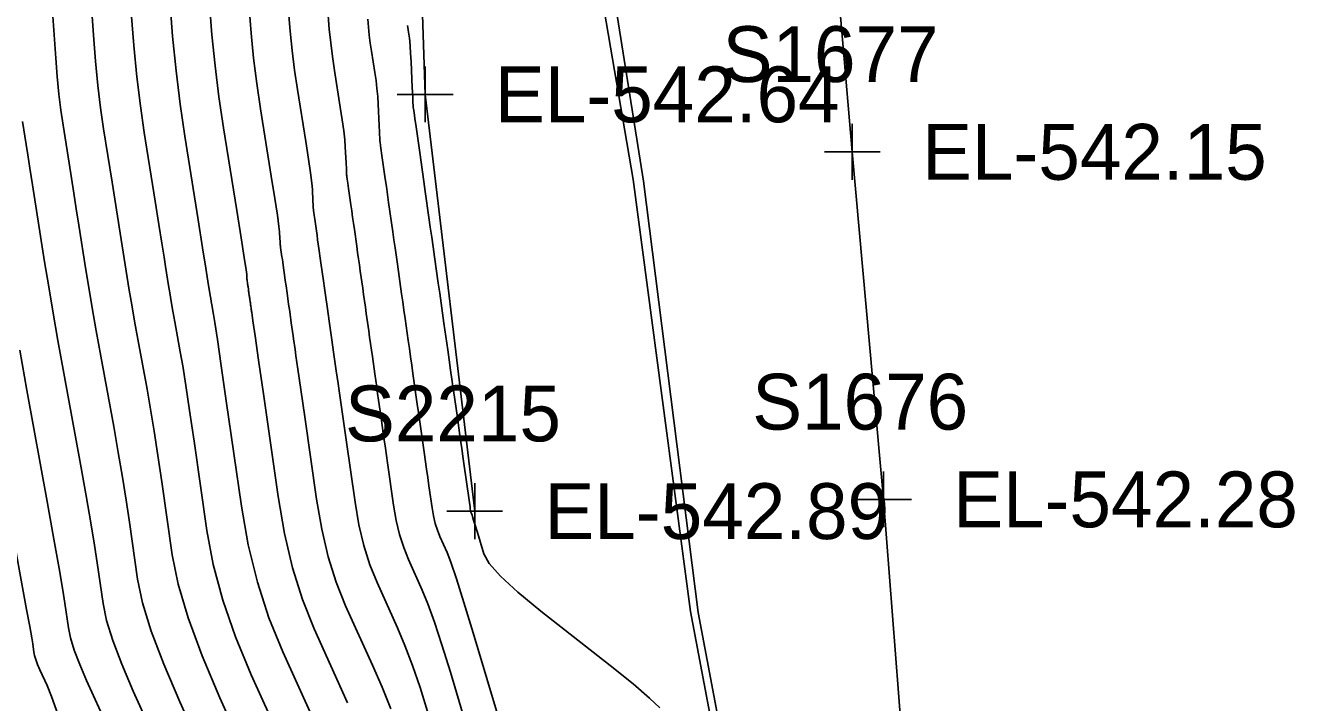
# Model space of a CAD drawing. Extents: x 1724534 to 1727318, y 657156 to 660047.
# Drawn here: x 1725501.3 to 1725592.2, y 658724.9 to 658773.4 of the extents above; entities that cross this region are included whole.
import ezdxf

# ---------------------------------------------------------------- set-up
doc = ezdxf.new("R2010")
doc.units = 0
for name, color, linetype in [('SURVEY - CONTOURS - Index with Text', 7, 'Continuous'), ('SURVEY - CONTOURS - Intermediate with optional Text', 7, 'Continuous'), ('SURVEY - DTM - Breaklines', 7, 'Continuous'), ('SURVEY - DTM - Breaklines - Points - Elevations', 7, 'Continuous'), ('SURVEY - DTM - Breaklines - Points - Locators', 7, 'Continuous'), ('SURVEY - DTM - Breaklines - Points - Numbers', 7, 'Continuous'), ('SURVEY - TRANSPORTATION - Features', 7, 'Continuous'), ('SURVEY - TRANSPORTATION - Features - Points - Elevations', 7, 'Continuous'), ('SURVEY - TRANSPORTATION - Features - Points - Locators', 7, 'Continuous'), ('SURVEY - TRANSPORTATION - Features - Points - Numbers', 7, 'Continuous'), ('SURVEY - UTILITIES - Electric (Underground) with Text', 7, 'Continuous'), ('SURVEY - UTILITIES - Fiber Optic Cable (Underground) with Text', 7, 'Continuous')]:
    doc.layers.add(name, color=color, linetype=linetype)

msp = doc.modelspace()

# ---------------------------------------------------------------- linework, layer by layer
at = {"layer": 'SURVEY - CONTOURS - Index with Text'}
for points in [[(1725508.859, 658774.321), (1725509.045, 658771.934), (1725509.261, 658769.703), (1725509.507, 658767.628), (1725509.785, 658765.709), (1725510.567, 658760.8), (1725510.833, 658759.126), (1725511.046, 658757.786), (1725511.206, 658756.779), (1725511.313, 658756.107), (1725511.526, 658754.758), (1725511.614, 658754.214), (1725511.719, 658753.597), (1725511.84, 658752.905), (1725511.978, 658752.138), (1725512.368, 658749.995), (1725512.539, 658748.992), (1725512.76, 658747.59), (1725513.03, 658745.79), (1725513.35, 658743.591), (1725514.268, 658737.195), (1725514.725, 658734.75), (1725515.409, 658732.214), (1725516.319, 658729.585), (1725517.455, 658726.864), (1725519.5, 658722.336)], [(1725522.963, 658774.097), (1725523.042, 658773.114), (1725523.143, 658772.13), (1725523.267, 658771.146), (1725523.412, 658770.162), (1725523.83, 658767.536), (1725523.97, 658766.619), (1725524.076, 658765.839), (1725524.148, 658765.194), (1725524.186, 658764.685), (1725524.243, 658763.51), (1725524.261, 658763.123), (1725524.275, 658762.846), (1725524.283, 658762.676), (1725524.287, 658762.616), (1725524.289, 658762.599), (1725524.298, 658762.539), (1725524.322, 658762.37), (1725524.361, 658762.093), (1725524.416, 658761.707), (1725524.582, 658760.533), (1725524.645, 658760.092), (1725524.708, 658759.65), (1725524.771, 658759.205), (1725524.834, 658758.76), (1725525.003, 658757.569), (1725525.067, 658757.121), (1725525.131, 658756.672), (1725525.195, 658756.222), (1725525.259, 658755.769), (1725525.431, 658754.561), (1725525.495, 658754.107), (1725525.56, 658753.651), (1725525.625, 658753.194), (1725525.69, 658752.735), (1725525.864, 658751.509), (1725525.93, 658751.048), (1725525.995, 658750.586), (1725526.061, 658750.122), (1725526.127, 658749.656), (1725526.304, 658748.411), (1725526.37, 658747.944), (1725526.437, 658747.474), (1725526.504, 658747.003), (1725526.571, 658746.53), (1725526.751, 658745.267), (1725526.83, 658744.71), (1725526.933, 658743.989), (1725527.06, 658743.101), (1725527.211, 658742.049), (1725527.646, 658739.021), (1725527.835, 658737.925), (1725528.076, 658736.908), (1725528.368, 658735.97), (1725528.712, 658735.111), (1725529.7, 658732.924), (1725530.103, 658731.941), (1725530.573, 658730.634), (1725531.108, 658729.003), (1725531.71, 658727.046), (1725533.403, 658721.396)], [(1725500.188, 658737.991), (1725501.361, 658731.538), (1725501.58, 658730.321), (1725501.723, 658729.502), (1725501.793, 658729.081), (1725501.878, 658728.489), (1725501.929, 658728.243), (1725502.02, 658727.948), (1725502.149, 658727.604), (1725502.318, 658727.211), (1725502.82, 658726.099), (1725503.139, 658725.293), (1725503.72, 658723.709), (1725504.564, 658721.345), (1725505.669, 658718.204), (1725506.416, 658716.07)]]:
    msp.add_lwpolyline(points, dxfattribs=at)
at = {"layer": 'SURVEY - CONTOURS - Intermediate with optional Text'}
for points in [[(1725505.802, 658777.801), (1725506.154, 658772.682), (1725506.299, 658770.823), (1725506.467, 658769.086), (1725506.659, 658767.47), (1725506.875, 658765.976), (1725507.484, 658762.153), (1725508.063, 658758.508), (1725508.209, 658757.585), (1725508.567, 658755.319), (1725508.715, 658754.406), (1725508.892, 658753.368), (1725509.096, 658752.205), (1725509.327, 658750.917), (1725509.983, 658747.316), (1725510.233, 658745.889), (1725510.492, 658744.309), (1725510.761, 658742.575), (1725511.038, 658740.689), (1725511.79, 658735.454), (1725512.215, 658733.341), (1725512.925, 658730.931), (1725513.922, 658728.222), (1725515.204, 658725.215), (1725519.004, 658716.798)], [(1725503.197, 658774.708), (1725503.45, 658771.043), (1725503.553, 658769.713), (1725503.673, 658768.469), (1725503.811, 658767.312), (1725503.966, 658766.242), (1725504.402, 658763.505), (1725504.741, 658761.369), (1725504.92, 658760.237), (1725505.106, 658759.064), (1725505.609, 658755.88), (1725505.817, 658754.598), (1725506.064, 658753.14), (1725506.351, 658751.506), (1725506.677, 658749.697), (1725507.597, 658744.637), (1725507.927, 658742.786), (1725508.225, 658741.027), (1725508.492, 658739.361), (1725508.727, 658737.787), (1725509.312, 658733.713), (1725509.666, 658732.017), (1725510.289, 658729.986), (1725511.181, 658727.619), (1725512.342, 658724.917), (1725515.798, 658717.265)], [(1725511.617, 658775.195), (1725511.82, 658772.614), (1725512.067, 658770.129), (1725512.359, 658767.738), (1725512.695, 658765.443), (1725513.649, 658759.448), (1725513.966, 658757.46), (1725514.199, 658755.995), (1725514.349, 658755.05), (1725514.512, 658754.023), (1725514.546, 658753.825), (1725514.585, 658753.604), (1725514.629, 658753.359), (1725514.754, 658752.674), (1725514.845, 658752.095), (1725515.027, 658750.871), (1725515.299, 658749.004), (1725515.661, 658746.492), (1725516.746, 658738.936), (1725517.236, 658736.159), (1725517.893, 658733.497), (1725518.717, 658730.948), (1725519.707, 658728.513), (1725522.57, 658722.173)], [(1725514.453, 658774.92), (1725514.631, 658772.703), (1725514.859, 658770.485), (1725515.138, 658768.265), (1725515.466, 658766.045), (1725516.409, 658760.122), (1725516.719, 658758.17), (1725516.941, 658756.757), (1725517.076, 658755.883), (1725517.123, 658755.547), (1725517.131, 658755.371), (1725517.134, 658755.313), (1725517.136, 658755.271), (1725517.137, 658755.246), (1725517.138, 658755.237), (1725517.138, 658755.234), (1725517.139, 658755.225), (1725517.143, 658755.2), (1725517.149, 658755.158), (1725517.157, 658755.1), (1725517.182, 658754.924), (1725517.192, 658754.858), (1725517.201, 658754.791), (1725517.21, 658754.724), (1725517.22, 658754.658), (1725517.245, 658754.479), (1725517.255, 658754.412), (1725517.264, 658754.344), (1725517.274, 658754.277), (1725517.284, 658754.209), (1725517.309, 658754.027), (1725517.319, 658753.959), (1725517.329, 658753.891), (1725517.339, 658753.822), (1725517.348, 658753.753), (1725517.375, 658753.569), (1725517.384, 658753.5), (1725517.394, 658753.43), (1725517.404, 658753.361), (1725517.414, 658753.291), (1725517.441, 658753.104), (1725517.451, 658753.034), (1725517.461, 658752.963), (1725517.471, 658752.892), (1725517.481, 658752.821), (1725517.508, 658752.632), (1725517.566, 658752.225), (1725517.72, 658751.149), (1725517.971, 658749.402), (1725518.318, 658746.984), (1725519.372, 658739.644), (1725519.83, 658736.987), (1725520.414, 658734.521), (1725521.123, 658732.246), (1725521.958, 658730.163), (1725524.352, 658724.861)], [(1725517.29, 658774.646), (1725517.435, 658772.84), (1725517.621, 658771.033), (1725517.847, 658769.226), (1725518.115, 658767.417), (1725518.883, 658762.593), (1725519.136, 658760.987), (1725519.319, 658759.784), (1725519.433, 658758.986), (1725519.477, 658758.593), (1725519.502, 658758.084), (1725519.51, 658757.916), (1725519.519, 658757.723), (1725519.521, 658757.696), (1725519.522, 658757.689), (1725519.525, 658757.663), (1725519.536, 658757.59), (1725519.553, 658757.47), (1725519.577, 658757.302), (1725519.649, 658756.794), (1725519.676, 658756.602), (1725519.703, 658756.411), (1725519.731, 658756.218), (1725519.859, 658755.315), (1725519.887, 658755.12), (1725519.942, 658754.729), (1725520.017, 658754.205), (1725520.044, 658754.008), (1725520.073, 658753.811), (1725520.101, 658753.613), (1725520.129, 658753.414), (1725520.204, 658752.882), (1725520.233, 658752.683), (1725520.261, 658752.482), (1725520.29, 658752.281), (1725520.318, 658752.079), (1725520.453, 658751.133), (1725520.482, 658750.929), (1725520.589, 658750.177), (1725520.654, 658749.72), (1725520.791, 658748.762), (1725521.001, 658747.302), (1725521.283, 658745.339), (1725522.13, 658739.437), (1725522.499, 658737.3), (1725522.968, 658735.317), (1725523.538, 658733.488), (1725524.21, 658731.812), (1725526.135, 658727.549), (1725526.821, 658725.967), (1725527.436, 658724.42)], [(1725520.127, 658774.371), (1725520.238, 658772.977), (1725520.382, 658771.582), (1725520.557, 658770.186), (1725520.764, 658768.79), (1725521.357, 658765.065), (1725521.553, 658763.803), (1725521.698, 658762.811), (1725521.791, 658762.09), (1725521.832, 658761.639), (1725521.872, 658760.797), (1725521.885, 658760.52), (1725521.895, 658760.321), (1725521.901, 658760.199), (1725521.904, 658760.156), (1725521.905, 658760.144), (1725521.912, 658760.101), (1725521.929, 658759.98), (1725521.957, 658759.781), (1725521.996, 658759.505), (1725522.116, 658758.663), (1725522.161, 658758.347), (1725522.206, 658758.03), (1725522.251, 658757.712), (1725522.296, 658757.392), (1725522.417, 658756.539), (1725522.463, 658756.218), (1725522.509, 658755.896), (1725522.555, 658755.573), (1725522.601, 658755.249), (1725522.724, 658754.383), (1725522.77, 658754.058), (1725522.816, 658753.731), (1725522.863, 658753.403), (1725522.909, 658753.074), (1725523.034, 658752.196), (1725523.081, 658751.865), (1725523.128, 658751.534), (1725523.175, 658751.201), (1725523.223, 658750.867), (1725523.35, 658749.975), (1725523.397, 658749.64), (1725523.445, 658749.304), (1725523.493, 658748.966), (1725523.541, 658748.627), (1725523.67, 658747.722), (1725523.742, 658747.215), (1725523.862, 658746.375), (1725524.031, 658745.202), (1725524.247, 658743.694), (1725524.888, 658739.229), (1725525.167, 658737.613), (1725525.522, 658736.113), (1725525.953, 658734.729), (1725526.461, 658733.461), (1725527.917, 658730.236), (1725528.462, 658728.954), (1725529.005, 658727.527), (1725529.545, 658725.955), (1725530.082, 658724.238)], [(1725525.8, 658773.822), (1725525.846, 658773.251), (1725525.905, 658772.679), (1725525.976, 658772.107), (1725526.061, 658771.534), (1725526.304, 658770.007), (1725526.387, 658769.436), (1725526.454, 658768.866), (1725526.506, 658768.298), (1725526.541, 658767.731), (1725526.613, 658766.223), (1725526.637, 658765.727), (1725526.665, 658765.153), (1725526.67, 658765.076), (1725526.673, 658765.055), (1725526.714, 658764.76), (1725526.835, 658763.909), (1725527.049, 658762.403), (1725527.13, 658761.837), (1725527.21, 658761.269), (1725527.291, 658760.699), (1725527.59, 658758.599), (1725527.671, 658758.025), (1725527.753, 658757.449), (1725527.917, 658756.29), (1725528.22, 658754.156), (1725528.303, 658753.572), (1725528.387, 658752.985), (1725528.47, 658752.396), (1725528.694, 658750.822), (1725528.778, 658750.231), (1725528.862, 658749.638), (1725528.947, 658749.042), (1725529.032, 658748.444), (1725529.344, 658746.247), (1725529.429, 658745.645), (1725529.832, 658742.812), (1725530.004, 658741.602), (1725530.09, 658741.001), (1725530.175, 658740.404), (1725530.404, 658738.814), (1725530.503, 658738.238), (1725530.629, 658737.704), (1725530.783, 658737.211), (1725530.964, 658736.76), (1725531.482, 658735.611), (1725531.744, 658734.929), (1725532.141, 658733.742), (1725532.672, 658732.05), (1725533.338, 658729.855), (1725535.294, 658723.327)], [(1725528.649, 658773.388), (1725528.666, 658773.228), (1725528.686, 658773.067), (1725528.71, 658772.907), (1725528.778, 658772.479), (1725528.804, 658772.252), (1725528.833, 658771.893), (1725528.863, 658771.401), (1725528.895, 658770.777), (1725528.984, 658768.936), (1725529.013, 658768.33), (1725529.034, 658767.895), (1725529.047, 658767.63), (1725529.053, 658767.535), (1725529.056, 658767.51), (1725529.07, 658767.415), (1725529.107, 658767.15), (1725529.169, 658766.716), (1725529.255, 658766.111), (1725529.516, 658764.273), (1725529.614, 658763.582), (1725529.713, 658762.889), (1725529.811, 658762.193), (1725529.911, 658761.494), (1725530.176, 658759.629), (1725530.275, 658758.928), (1725530.375, 658758.225), (1725530.475, 658757.519), (1725530.576, 658756.81), (1725530.845, 658754.917), (1725530.946, 658754.206), (1725531.047, 658753.492), (1725531.149, 658752.776), (1725531.251, 658752.057), (1725531.524, 658750.135), (1725531.626, 658749.414), (1725531.729, 658748.689), (1725531.936, 658747.232), (1725532.213, 658745.283), (1725532.317, 658744.55), (1725532.421, 658743.815), (1725532.526, 658743.077), (1725532.632, 658742.336), (1725532.913, 658740.357), (1725533.006, 658739.7), (1725533.075, 658739.215), (1725533.119, 658738.901), (1725533.14, 658738.758), (1725533.162, 658738.606), (1725533.171, 658738.551), (1725533.183, 658738.5), (1725533.198, 658738.452), (1725533.215, 658738.409), (1725533.265, 658738.299), (1725533.303, 658738.191), (1725533.38, 658737.948), (1725533.495, 658737.571), (1725533.649, 658737.06), (1725534.111, 658735.517), (1725534.496, 658734.828), (1725535.304, 658733.917), (1725536.535, 658732.784), (1725538.189, 658731.428), (1725543.163, 658727.519), (1725544.802, 658726.204), (1725545.987, 658725.194), (1725546.719, 658724.487)], [(1725501.056, 658766.509), (1725501.319, 658764.858), (1725501.436, 658764.124), (1725501.588, 658763.16), (1725501.777, 658761.966), (1725502.65, 658756.441), (1725502.919, 658754.789), (1725503.237, 658752.911), (1725503.606, 658750.807), (1725504.026, 658748.476), (1725505.212, 658741.958), (1725505.621, 658739.683), (1725505.958, 658737.746), (1725506.223, 658736.146), (1725506.415, 658734.885), (1725506.834, 658731.971), (1725507.087, 658730.759), (1725507.532, 658729.307), (1725508.17, 658727.614), (1725509.001, 658725.682), (1725511.472, 658720.21)], [(1725500.862, 658750.107), (1725501.375, 658747.255), (1725502.827, 658739.279), (1725503.315, 658736.58), (1725503.69, 658734.464), (1725503.953, 658732.932), (1725504.104, 658731.983), (1725504.356, 658730.23), (1725504.508, 658729.501), (1725504.776, 658728.627), (1725505.16, 658727.609), (1725505.659, 658726.447), (1725507.146, 658723.154)]]:
    msp.add_lwpolyline(points, dxfattribs=at)
at = {"layer": 'SURVEY - DTM - Breaklines'}
msp.add_lwpolyline([(1725533.454, 658738.584), (1725529.91, 658768.444), (1725528.895, 658798.433), (1725528.35, 658828.444), (1725532.274, 658858.683), (1725531.303, 658888.673), (1725527.687, 658918.53), (1725523.837, 658948.374), (1725524.63, 658981.767), (1725524.814, 658996.206), (1725524.72, 658997.154)], dxfattribs=at)
at = {"layer": 'SURVEY - DTM - Breaklines - Points - Locators'}
for p, q in [((1725529.91, 658770.444), (1725529.91, 658766.444)), ((1725531.91, 658768.444), (1725527.91, 658768.444)), ((1725533.454, 658740.584), (1725533.454, 658736.584)), ((1725535.454, 658738.584), (1725531.454, 658738.584))]:
    msp.add_line(p, q, dxfattribs=at)
at = {"layer": 'SURVEY - TRANSPORTATION - Features'}
msp.add_lwpolyline([(1725570.831, 658646.253), (1725568.796, 658661.122), (1725567.732, 658676.049), (1725566.054, 658695.422), (1725564.662, 658714.496), (1725562.732, 658739.426), (1725560.5, 658764.327), (1725558.347, 658789.335), (1725556.113, 658814.238), (1725553.973, 658839.149), (1725552.257, 658864.379), (1725550.906, 658889.348), (1725550.236, 658914.341), (1725548.733, 658939.305), (1725548.535, 658964.315)], dxfattribs=at)
at = {"layer": 'SURVEY - TRANSPORTATION - Features - Points - Locators'}
for p, q in [((1725560.5, 658766.327), (1725560.5, 658762.327)), ((1725562.5, 658764.327), (1725558.5, 658764.327)), ((1725562.732, 658741.426), (1725562.732, 658737.426)), ((1725564.732, 658739.426), (1725560.732, 658739.426))]:
    msp.add_line(p, q, dxfattribs=at)
at = {"layer": 'SURVEY - UTILITIES - Electric (Underground) with Text'}
msp.add_lwpolyline([(1725538.314, 658827.699), (1725538.61, 658810.76), (1725539.309, 658794.446), (1725544.796, 658762.344), (1725548.909, 658731.403), (1725555.845, 658694.728), (1725557.583, 658674.802)], dxfattribs=at)
at = {"layer": 'SURVEY - UTILITIES - Fiber Optic Cable (Underground) with Text'}
msp.add_lwpolyline([(1725538.949, 658827.551), (1725539.433, 658810.741), (1725540.407, 658794.551), (1725545.54, 658762.23), (1725549.453, 658731.328), (1725556.372, 658694.759), (1725557.942, 658674.857)], dxfattribs=at)

# ---------------------------------------------------------------- texts
at = {"layer": 'SURVEY - DTM - Breaklines - Points - Elevations'}
for s, p in [('EL-542.64', (1725534.91, 658766.444)), ('EL-542.89', (1725538.454, 658736.584))]:
    msp.add_text(s, height=4, dxfattribs=at).set_placement(p)
at = {"layer": 'SURVEY - DTM - Breaklines - Points - Numbers'}
msp.add_text('S2215', height=4, dxfattribs=at).set_placement((1725524.166, 658743.584))
at = {"layer": 'SURVEY - TRANSPORTATION - Features - Points - Elevations'}
for s, p in [('EL-542.15', (1725565.5, 658762.327)), ('EL-542.28', (1725567.732, 658737.426))]:
    msp.add_text(s, height=4, dxfattribs=at).set_placement(p)
at = {"layer": 'SURVEY - TRANSPORTATION - Features - Points - Numbers'}
for s, p in [('S1677', (1725551.212, 658769.327)), ('S1676', (1725553.334, 658744.426))]:
    msp.add_text(s, height=4, dxfattribs=at).set_placement(p)

doc.saveas('drawing.dxf')
